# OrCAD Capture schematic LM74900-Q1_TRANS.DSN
size Custom; title: LM749x0-Q1 Automotive Ideal Diode With Circuit Breaker,; rev: 1.0; note: Datasheet: SNOSDE6; note: Undervoltage and Overvoltage Protection With Fault Output
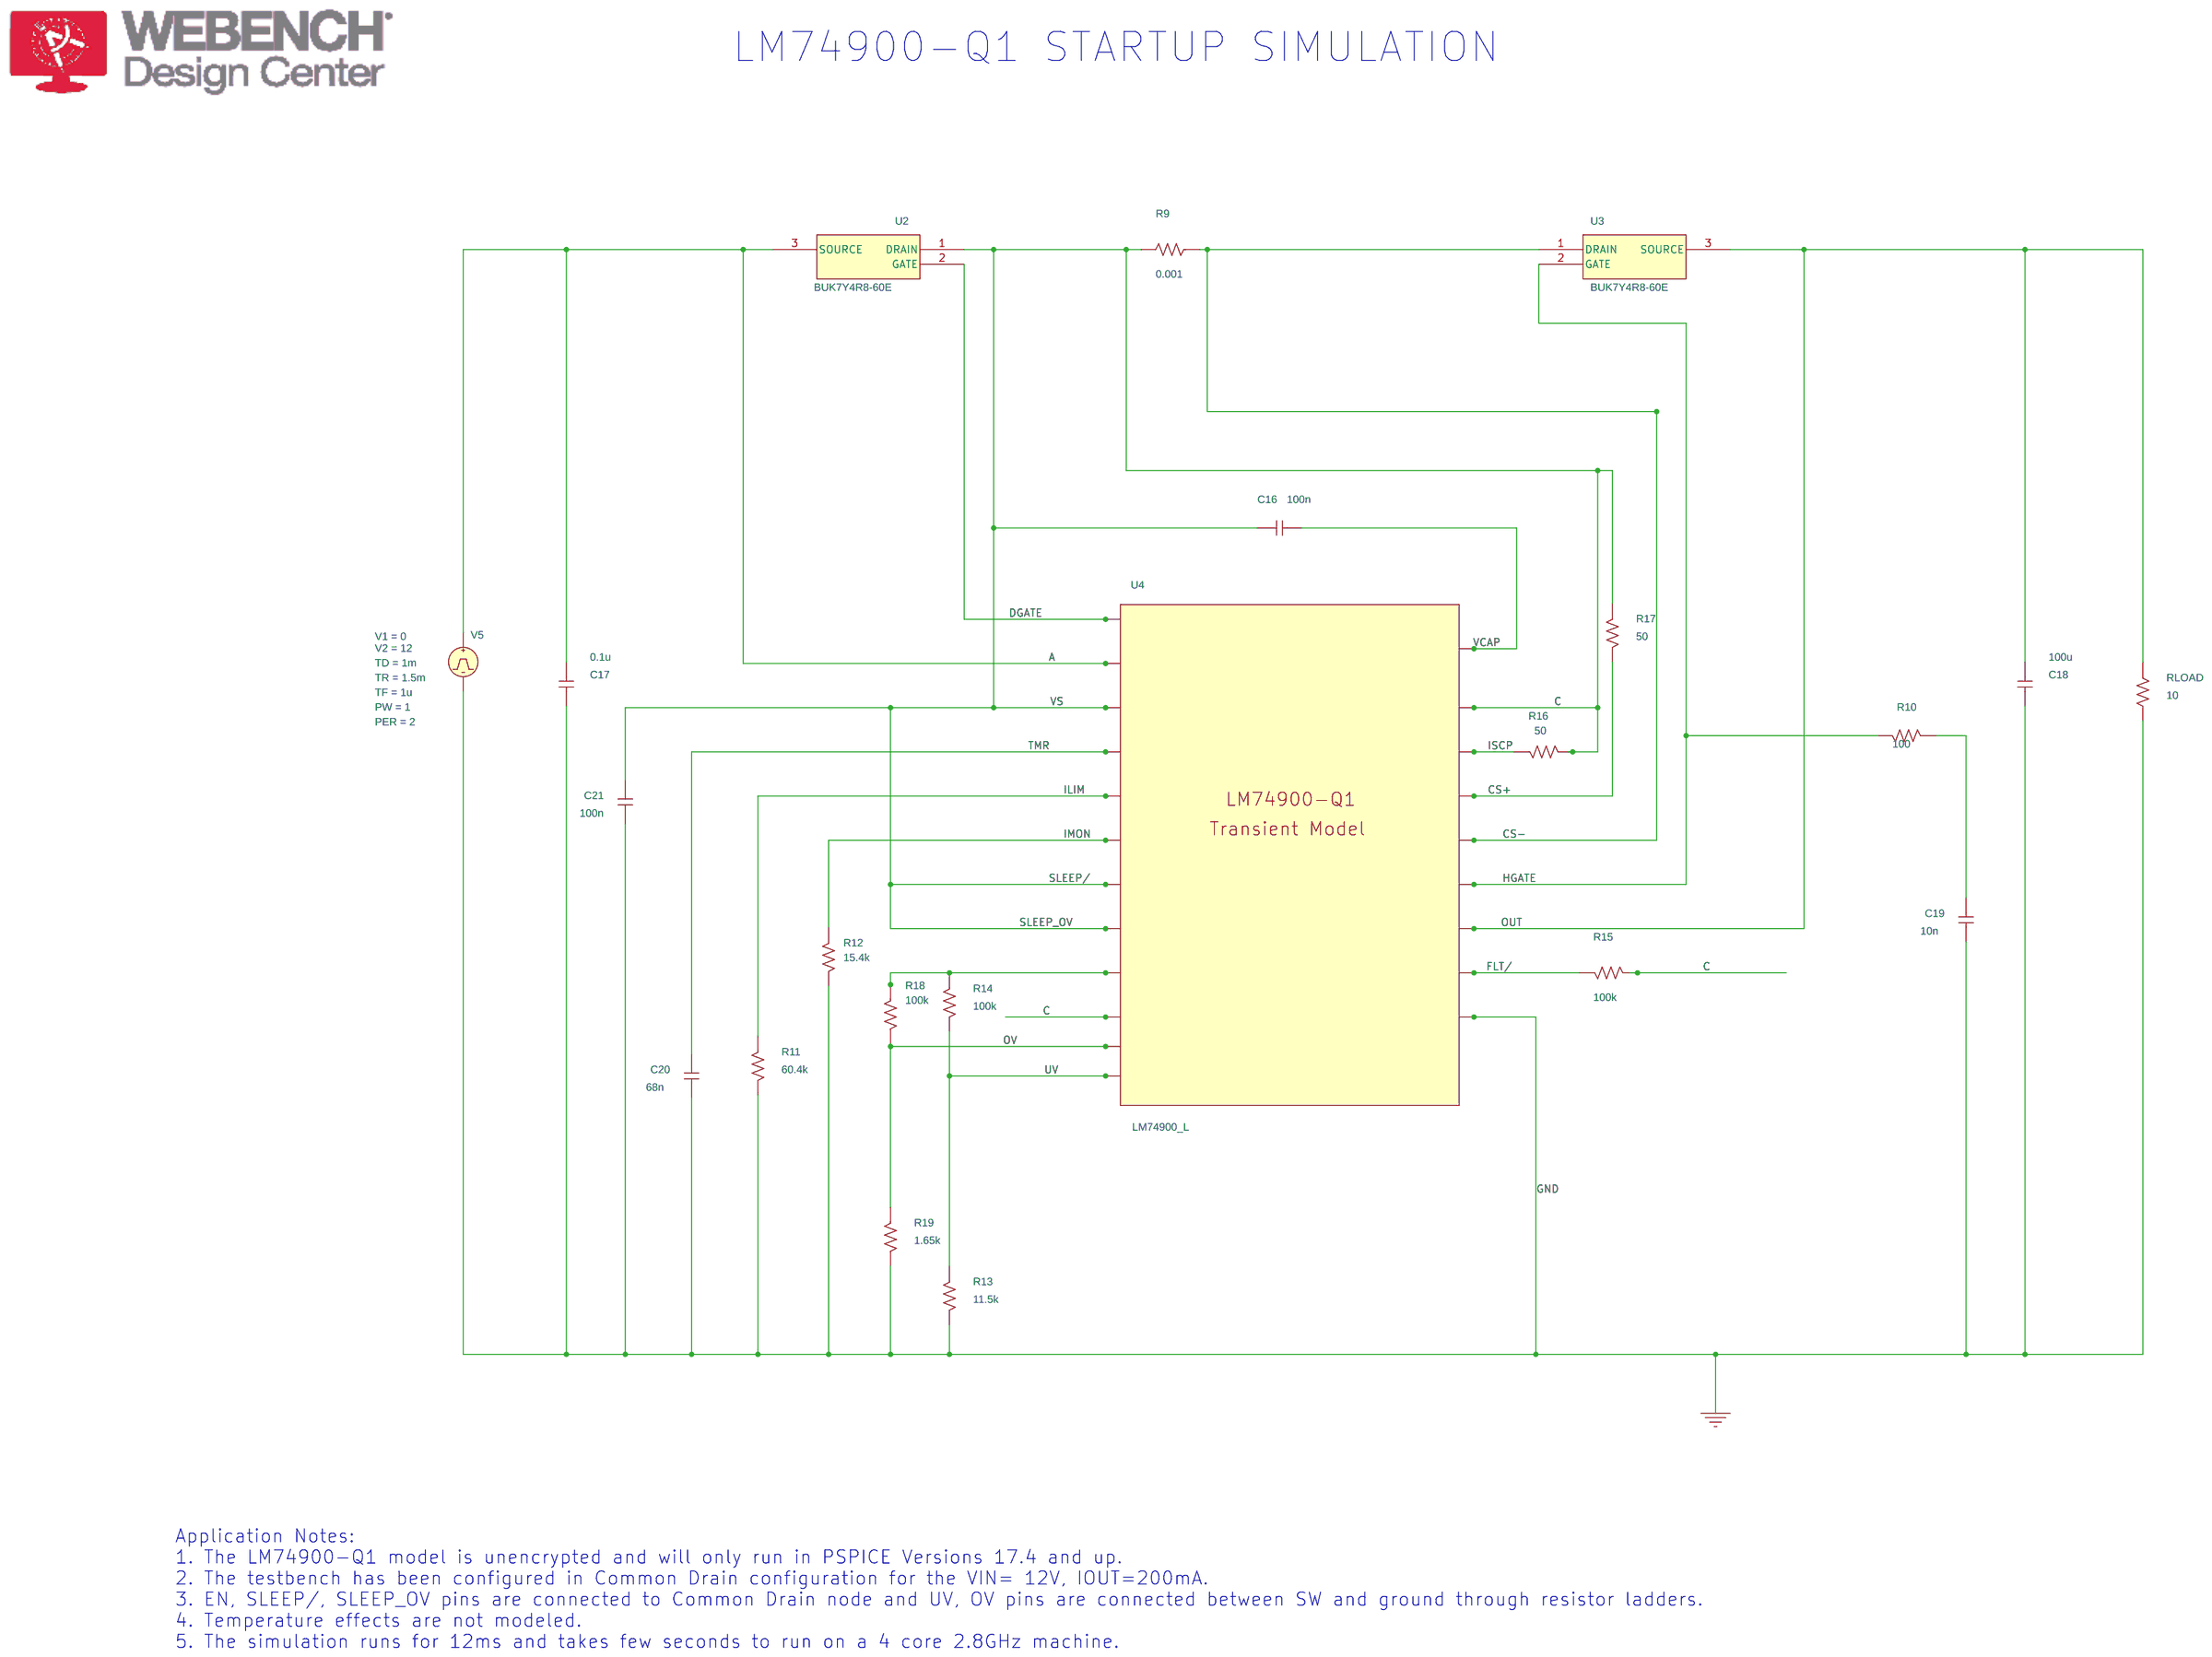
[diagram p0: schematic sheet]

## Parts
C16  100n  [RAD/CK05]
C17  0.1u  [RAD/CK05]
C18  100u  [RAD/CK05]
C19  10n  [RAD/CK05]
C20  68n  [RAD/CK05]
C21  100n  [RAD/CK05]
R9  0.001  [AX/RC05]
R10  100  [AX/RC05]
R11  60.4k  [AX/RC05]
R12  15.4k  [AX/RC05]
R13  11.5k  [AX/RC05]
R14  100k  [AX/RC05]
R15  100k  [AX/RC05]
R16  50  [AX/RC05]
R17  50  [AX/RC05]
R18  100k  [AX/RC05]
R19  1.65k  [AX/RC05]
RLOAD  10  [AX/RC05]
U2  BUK7Y4R8-60E
U3  BUK7Y4R8-60E
U4  LM74900_L
V5  VPULSE

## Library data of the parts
C16-C21 = C
R9-R19 RLOAD = R
U2 U3 = BUK7Y4R8-60E
U4 = LM74900_L_0
V5 = VPULSE: PER: 2; PW: 1; TD: 1m; TF: 1u; TR: 1.5m; V1: 0; V2: 12

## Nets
0: C17.2 C18.2 C19.1 C20.1 C21.1 R11.2 R12.2 R13.2 R19.2 RLOAD.2 U4.GND V5.2(-)
A: C17.1 U2.3(SOURCE) U4.A V5.1(+)
C: C16.1 C21.2 R9.2 R15.2 R16.2 R17.1 U2.1(DRAIN) U4.C U4.EN U4.SLEEP/ U4.SLEEP_OV U4.VS
CS+: R17.2 U4.CS+
CS-: R9.1 U3.1(DRAIN) U4.CS-
DGATE: U2.2(GATE) U4.DGATE
FLT/: R15.1 U4.FLT/
HGATE: R10.2 U3.2(GATE) U4.HGATE
ILIM: R11.1 U4.ILIM
IMON: R12.1 U4.IMON
ISCP: R16.1 U4.ISCP
OUT: C18.1 RLOAD.1 U3.3(SOURCE) U4.OUT
OV: R18.2 R19.1 U4.OV
TMR: C20.2 U4.TMR
UV: R13.1 R14.2 U4.UV
VCAP: C16.2 U4.VCAP
N16779081: C19.2 R10.1
N16794357: R14.1 R18.1 U4.SW

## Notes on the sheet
- LM74900-Q1 STARTUP SIMULATION
- Application Notes:
  1. The LM74900-Q1 model is unencrypted and will only run in PSPICE Versions 17.4 and up.
  2. The testbench has been configured in Common Drain configuration for the VIN= 12V, IOUT=200mA.
  3. EN, SLEEP/, SLEEP_OV pins are connected to Common Drain node and UV, OV pins are connected between SW and ground through resistor ladders.
  4. Temperature effects are not modeled.
  5. The simulation runs for 12ms and takes few seconds to run on a 4 core 2.8GHz machine.
